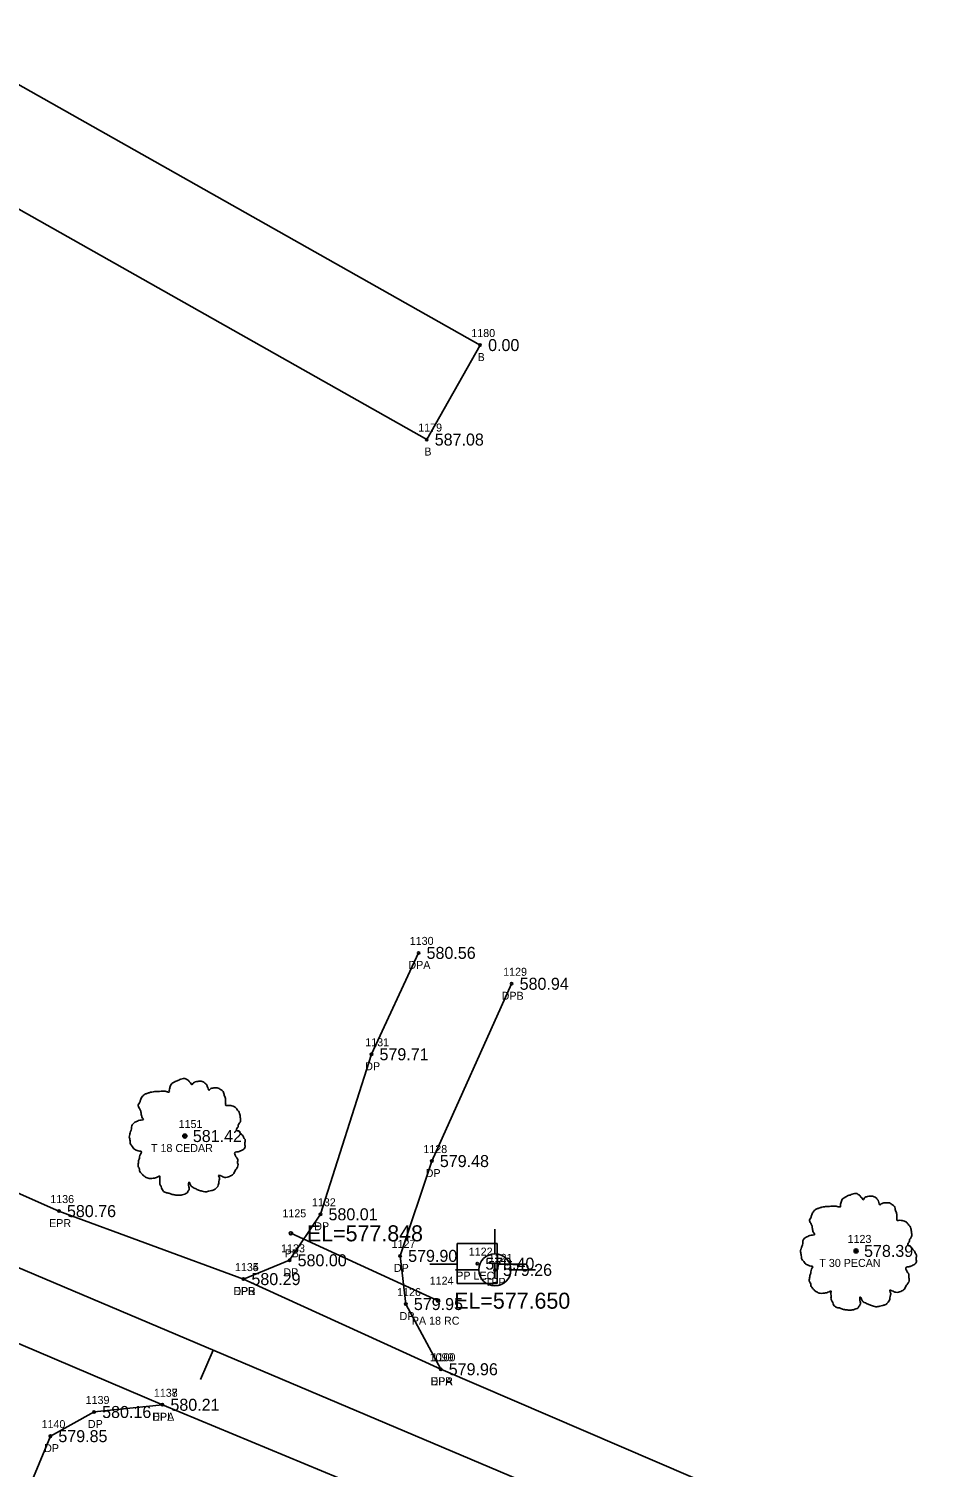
# Model space of a CAD drawing. Extents: x 1664393 to 1667175, y 987029 to 988607.
# Drawn here: x 1665100.7 to 1665215.9, y 987913.2 to 988093 of the extents above; entities that cross this region are included whole.
import ezdxf

# ---------------------------------------------------------------- set-up
doc = ezdxf.new("R2010")
doc.units = 0
for name, color, linetype in [('RD_EX_Bldg', 7, 'Continuous'), ('RD_EX_Bldg_txCode', 7, 'Continuous'), ('RD_EX_DR_Pipe', 7, 'Continuous'), ('RD_EX_DR_Pipe_txCode', 7, 'Continuous'), ('RD_EX_Driveway', 7, 'Continuous'), ('RD_EX_Driveway_txCode', 7, 'Continuous'), ('RD_EX_Road', 7, 'Continuous'), ('RD_EX_Road_txCode', 7, 'Continuous'), ('RD_EX_TX_Bldg_ELEV', 7, 'Continuous'), ('RD_EX_TX_Driveway_ELEV', 7, 'Continuous'), ('RD_EX_TX_Road_ELEV', 7, 'Continuous'), ('RD_EX_TX_UT_ELEV', 7, 'Continuous'), ('RD_EX_TX_VEG_ELEV', 7, 'Continuous'), ('RD_EX_UT', 7, 'Continuous'), ('RD_EX_UT_txCode', 7, 'Continuous'), ('RD_EX_VEG', 7, 'Continuous'), ('RD_EX_VEG_txCode', 7, 'Continuous'), ('RD_HC_Cl', 7, 'Continuous'), ('RD_HC_Data_Tic', 7, 'Continuous'), ('RD_HC_Survey_ELEV', 7, 'Continuous'), ('RD_SMD_Locator', 7, 'Continuous'), ('RD_TX_Pipe_ElevEX', 7, 'Continuous')]:
    doc.layers.add(name, color=color, linetype=linetype)

msp = doc.modelspace()

# ---------------------------------------------------------------- linework, layer by layer
at = {"layer": 'RD_EX_Bldg'}
msp.add_lwpolyline([(1665080.42, 988081.16), (1665150.45, 988041.63), (1665157.12, 988053.44), (1665087.09, 988092.97), (1665080.42, 988081.16)], dxfattribs=at)
at = {"layer": 'RD_EX_DR_Pipe'}
msp.add_line((1665151.88, 987934), (1665133.48, 987942.42), dxfattribs=at)
at = {"layer": 'RD_EX_Driveway'}
for points in [[(1665149.43, 987977.47), (1665143.55, 987964.8), (1665137.18, 987944.8), (1665133.32, 987939.05), (1665127.55, 987936.7)], [(1665152.2, 987925.43), (1665147.84, 987933.58), (1665147.13, 987939.6), (1665151.09, 987951.45), (1665161.06, 987973.61)], [(1665117.43, 987920.99), (1665108.9, 987920.09), (1665103.43, 987917.07), (1665098.7, 987905.61), (1665086.52, 987910.5), (1665090.17, 987920.87), (1665090.28, 987927.13), (1665086.22, 987934.27)]]:
    msp.add_lwpolyline(points, dxfattribs=at)
at = {"layer": 'RD_EX_Road'}
for points in [[(1665506.06, 987776.52), (1665471.95, 987789.57), (1665426.52, 987809.19), (1665380.33, 987828.78), (1665335.61, 987847.53), (1665288.25, 987866.82), (1665242.34, 987886.56), (1665197.07, 987906.16), (1665152.2, 987925.43), (1665127.55, 987936.7), (1665104.5, 987945.2), (1665059.19, 987965.3), (1665013.63, 987984.66), (1664966.38, 988005.06), (1664921.66, 988023.83), (1664875.55, 988043.8)], [(1665498.75, 987759.37), (1665465.87, 987774.2), (1665419.78, 987793.88), (1665373.62, 987813.14), (1665327.95, 987832.31), (1665281.42, 987852.3), (1665236.13, 987871.34), (1665189.6, 987890.71), (1665143.92, 987909.97), (1665117.43, 987920.99), (1665086.22, 987934.27), (1665051.62, 987948.55), (1665005.38, 987968.44), (1664960.17, 987987.67), (1664913.53, 988007.62), (1664868.21, 988026.81)]]:
    msp.add_lwpolyline(points, dxfattribs=at)
at = {"layer": 'RD_EX_UT'}
for p, q in [((1665158.97, 987942.92), (1665158.97, 987939.85)), ((1665159.26, 987941.14), (1665154.26, 987941.14)), ((1665154.26, 987941.14), (1665154.26, 987936.14)), ((1665159.26, 987936.14), (1665159.26, 987941.14)), ((1665150.82, 987938.58), (1665154.29, 987938.58)), ((1665154.04, 987937.86), (1665156.97, 987937.86)), ((1665159.18, 987938.58), (1665162.82, 987938.58)), ((1665160.97, 987937.86), (1665164.04, 987937.86)), ((1665154.26, 987936.14), (1665159.26, 987936.14))]:
    msp.add_line(p, q, dxfattribs=at)
msp.add_circle((1665158.97, 987937.85), 2, dxfattribs=at)
at = {"layer": 'RD_EX_VEG'}
for centre, radius in [((1665120.23, 987954.58), 0.25), ((1665120.22, 987954.56), 0.0001), ((1665204.09, 987940.22), 0.25), ((1665204.08, 987940.2), 0.0001)]:
    msp.add_circle(centre, radius, dxfattribs=at)
for points in [[(1665120.36, 987961.75), (1665120.06, 987961.78), (1665119.74, 987961.68), (1665119.49, 987961.58), (1665119.26, 987961.5), (1665119.04, 987961.4), (1665118.74, 987961.23), (1665118.51, 987961.03), (1665118.39, 987960.78), (1665118.34, 987960.55), (1665118.29, 987960.28), (1665118.29, 987960.1), (1665118.16, 987960.08), (1665118.01, 987960.1), (1665117.76, 987960.18), (1665117.51, 987960.18), (1665117.26, 987960.18), (1665116.91, 987960.15), (1665116.56, 987960.15), (1665116.29, 987960.1), (1665115.96, 987960.05), (1665115.59, 987959.93), (1665115.24, 987959.8), (1665114.94, 987959.55), (1665114.69, 987959.08), (1665114.56, 987958.73), (1665114.41, 987958.48), (1665114.56, 987958.03), (1665114.74, 987957.68), (1665114.76, 987957.48), (1665114.84, 987957.05), (1665114.94, 987956.83), (1665115.06, 987956.63), (1665114.99, 987956.6), (1665114.61, 987956.55), (1665114.31, 987956.45), (1665113.89, 987956.23), (1665113.66, 987956), (1665113.56, 987955.68), (1665113.54, 987955.33), (1665113.44, 987955.13), (1665113.36, 987954.85), (1665113.34, 987954.78), (1665113.29, 987954.45), (1665113.39, 987954), (1665113.41, 987953.65), (1665113.54, 987953.43), (1665113.69, 987953.25), (1665113.86, 987953), (1665114.26, 987952.78), (1665114.59, 987952.68), (1665114.79, 987952.65), (1665114.61, 987952.15), (1665114.56, 987951.8), (1665114.44, 987951.4), (1665114.44, 987951.33), (1665114.39, 987950.86), (1665114.54, 987950.53), (1665114.61, 987950.16), (1665114.79, 987949.93), (1665115.06, 987949.63), (1665115.39, 987949.41), (1665115.89, 987949.28), (1665116.29, 987949.31), (1665116.86, 987949.48), (1665117.11, 987949.56), (1665117.09, 987949.38), (1665117.11, 987949.01), (1665117.11, 987948.58), (1665117.26, 987948.26), (1665117.36, 987947.98), (1665117.51, 987947.73), (1665117.84, 987947.51), (1665118.24, 987947.43), (1665118.66, 987947.28), (1665119.11, 987947.21), (1665119.61, 987947.18), (1665120.21, 987947.33), (1665120.49, 987947.46), (1665120.59, 987947.63), (1665120.79, 987948.01), (1665120.74, 987948.23), (1665120.76, 987948.83), (1665120.86, 987948.66), (1665121.04, 987948.31), (1665121.54, 987948.01), (1665121.94, 987947.83), (1665122.41, 987947.68), (1665122.71, 987947.61), (1665123.19, 987947.68), (1665123.56, 987947.76), (1665123.93, 987947.88), (1665124.23, 987948.16), (1665124.41, 987948.43), (1665124.46, 987948.71), (1665124.53, 987949.08), (1665124.58, 987949.26)], [(1665124.58, 987949.26), (1665124.51, 987949.43), (1665124.46, 987949.68), (1665124.53, 987949.66), (1665124.71, 987949.61), (1665124.98, 987949.48), (1665125.21, 987949.41), (1665125.53, 987949.43), (1665125.81, 987949.53), (1665126.26, 987949.81), (1665126.53, 987950.28), (1665126.81, 987950.68), (1665126.88, 987951.01), (1665126.83, 987951.23), (1665126.81, 987951.73), (1665126.61, 987951.98), (1665126.56, 987952.1), (1665126.46, 987952.5), (1665126.53, 987952.55), (1665126.81, 987952.6), (1665127.18, 987952.73), (1665127.46, 987952.85), (1665127.68, 987953.03), (1665127.76, 987953.25), (1665127.73, 987953.65), (1665127.78, 987954.05), (1665127.71, 987954.2), (1665127.61, 987954.35), (1665127.53, 987954.55), (1665127.38, 987954.7), (1665127.28, 987954.85), (1665127.18, 987954.95), (1665127.06, 987955.1), (1665126.88, 987955.23), (1665126.73, 987955.28), (1665126.68, 987955.43), (1665126.83, 987955.63), (1665126.88, 987955.73), (1665126.91, 987955.95), (1665127.13, 987956.3), (1665127.18, 987956.7), (1665127.13, 987957.13), (1665127.08, 987957.4), (1665126.93, 987957.68), (1665126.73, 987957.93), (1665126.61, 987958.1), (1665126.43, 987958.23), (1665126.11, 987958.35), (1665125.86, 987958.4), (1665125.51, 987958.4), (1665125.31, 987958.45), (1665125.33, 987958.5), (1665125.33, 987958.65), (1665125.33, 987958.93), (1665125.26, 987959.38), (1665125.11, 987959.88), (1665125.11, 987959.9), (1665125.01, 987960.15), (1665124.78, 987960.35), (1665124.61, 987960.45), (1665124.41, 987960.58), (1665124.16, 987960.6), (1665123.86, 987960.6), (1665123.59, 987960.55), (1665123.39, 987960.45), (1665123.21, 987960.33), (1665123.14, 987960.48), (1665123.04, 987960.78), (1665122.99, 987960.93), (1665122.84, 987961.1), (1665122.61, 987961.3), (1665122.16, 987961.43), (1665121.54, 987961.35), (1665121.24, 987961.15), (1665121.09, 987960.98), (1665121.04, 987961.1), (1665120.84, 987961.3), (1665120.74, 987961.48), (1665120.56, 987961.6), (1665120.41, 987961.7), (1665120.31, 987961.75)], [(1665204.22, 987947.39), (1665203.92, 987947.41), (1665203.6, 987947.31), (1665203.35, 987947.21), (1665203.12, 987947.14), (1665202.9, 987947.04), (1665202.6, 987946.87), (1665202.37, 987946.67), (1665202.25, 987946.42), (1665202.2, 987946.19), (1665202.15, 987945.92), (1665202.15, 987945.74), (1665202.02, 987945.72), (1665201.87, 987945.74), (1665201.62, 987945.82), (1665201.37, 987945.82), (1665201.12, 987945.82), (1665200.77, 987945.79), (1665200.42, 987945.79), (1665200.15, 987945.74), (1665199.82, 987945.69), (1665199.45, 987945.57), (1665199.1, 987945.44), (1665198.8, 987945.19), (1665198.55, 987944.72), (1665198.42, 987944.37), (1665198.27, 987944.12), (1665198.42, 987943.67), (1665198.6, 987943.32), (1665198.62, 987943.12), (1665198.7, 987942.69), (1665198.8, 987942.47), (1665198.92, 987942.27), (1665198.85, 987942.24), (1665198.47, 987942.19), (1665198.17, 987942.09), (1665197.75, 987941.87), (1665197.52, 987941.64), (1665197.42, 987941.32), (1665197.4, 987940.97), (1665197.3, 987940.77), (1665197.22, 987940.49), (1665197.2, 987940.42), (1665197.15, 987940.09), (1665197.25, 987939.64), (1665197.27, 987939.29), (1665197.4, 987939.07), (1665197.55, 987938.89), (1665197.72, 987938.64), (1665198.12, 987938.42), (1665198.45, 987938.32), (1665198.65, 987938.29), (1665198.47, 987937.79), (1665198.42, 987937.44), (1665198.3, 987937.04), (1665198.3, 987936.97), (1665198.25, 987936.49), (1665198.4, 987936.17), (1665198.47, 987935.79), (1665198.65, 987935.57), (1665198.92, 987935.27), (1665199.25, 987935.05), (1665199.75, 987934.92), (1665200.15, 987934.95), (1665200.72, 987935.12), (1665200.97, 987935.2), (1665200.95, 987935.02), (1665200.97, 987934.65), (1665200.97, 987934.22), (1665201.12, 987933.9), (1665201.22, 987933.62), (1665201.37, 987933.37), (1665201.7, 987933.15), (1665202.1, 987933.07), (1665202.52, 987932.92), (1665202.97, 987932.85), (1665203.47, 987932.82), (1665204.07, 987932.97), (1665204.35, 987933.1), (1665204.45, 987933.27), (1665204.65, 987933.65), (1665204.6, 987933.87), (1665204.62, 987934.47), (1665204.72, 987934.3), (1665204.89, 987933.95), (1665205.39, 987933.65), (1665205.79, 987933.47), (1665206.27, 987933.32), (1665206.57, 987933.25), (1665207.04, 987933.32), (1665207.42, 987933.4), (1665207.79, 987933.52), (1665208.09, 987933.8), (1665208.27, 987934.07), (1665208.32, 987934.35), (1665208.39, 987934.72), (1665208.44, 987934.9)], [(1665208.44, 987934.9), (1665208.37, 987935.07), (1665208.32, 987935.32), (1665208.39, 987935.3), (1665208.57, 987935.25), (1665208.84, 987935.12), (1665209.07, 987935.05), (1665209.39, 987935.07), (1665209.67, 987935.17), (1665210.12, 987935.45), (1665210.39, 987935.92), (1665210.67, 987936.32), (1665210.74, 987936.64), (1665210.69, 987936.87), (1665210.67, 987937.37), (1665210.47, 987937.62), (1665210.42, 987937.74), (1665210.32, 987938.14), (1665210.39, 987938.19), (1665210.67, 987938.24), (1665211.04, 987938.37), (1665211.32, 987938.49), (1665211.54, 987938.67), (1665211.62, 987938.89), (1665211.59, 987939.29), (1665211.64, 987939.69), (1665211.57, 987939.84), (1665211.47, 987939.99), (1665211.39, 987940.19), (1665211.24, 987940.34), (1665211.14, 987940.49), (1665211.04, 987940.59), (1665210.92, 987940.74), (1665210.74, 987940.87), (1665210.59, 987940.92), (1665210.54, 987941.07), (1665210.69, 987941.27), (1665210.74, 987941.37), (1665210.77, 987941.59), (1665210.99, 987941.94), (1665211.04, 987942.34), (1665210.99, 987942.77), (1665210.94, 987943.04), (1665210.79, 987943.32), (1665210.59, 987943.57), (1665210.47, 987943.74), (1665210.29, 987943.87), (1665209.97, 987943.99), (1665209.72, 987944.04), (1665209.37, 987944.04), (1665209.17, 987944.09), (1665209.19, 987944.14), (1665209.19, 987944.29), (1665209.19, 987944.57), (1665209.12, 987945.02), (1665208.97, 987945.52), (1665208.97, 987945.54), (1665208.87, 987945.79), (1665208.64, 987945.99), (1665208.47, 987946.09), (1665208.27, 987946.22), (1665208.02, 987946.24), (1665207.72, 987946.24), (1665207.44, 987946.19), (1665207.24, 987946.09), (1665207.07, 987945.97), (1665206.99, 987946.12), (1665206.89, 987946.42), (1665206.84, 987946.57), (1665206.69, 987946.74), (1665206.47, 987946.94), (1665206.02, 987947.06), (1665205.39, 987946.99), (1665205.09, 987946.79), (1665204.94, 987946.62), (1665204.89, 987946.74), (1665204.69, 987946.94), (1665204.6, 987947.11), (1665204.42, 987947.24), (1665204.27, 987947.34), (1665204.17, 987947.39)]]:
    msp.add_spline(points, degree=3, dxfattribs=at)
at = {"layer": 'RD_HC_Cl'}
msp.add_line((1666160.05, 987489.41), (1664963.07, 987995.8), dxfattribs=at)
at = {"layer": 'RD_HC_Data_Tic'}
msp.add_line((1665123.76, 987927.82), (1665122.2, 987924.13), dxfattribs=at)
at = {"layer": 'RD_SMD_Locator'}
for centre, radius in [((1665157.12, 988053.44), 0.15), ((1665150.45, 988041.63), 0.15), ((1665149.43, 987977.47), 0.15), ((1665161.06, 987973.61), 0.15), ((1665143.55, 987964.8), 0.15), ((1665120.23, 987954.58), 0.15), ((1665151.09, 987951.45), 0.15), ((1665104.5, 987945.2), 0.15), ((1665137.18, 987944.8), 0.15), ((1665133.48, 987942.42), 0.2), ((1665147.13, 987939.6), 0.15), ((1665204.09, 987940.22), 0.15), ((1665133.32, 987939.05), 0.15), ((1665156.76, 987938.63), 0.15), ((1665158.97, 987937.85), 0.15), ((1665127.55, 987936.7), 0.15), ((1665127.55, 987936.7), 0.15), ((1665151.88, 987934), 0.2), ((1665147.84, 987933.58), 0.15), ((1665152.2, 987925.43), 0.15), ((1665152.2, 987925.43), 0.15), ((1665108.9, 987920.09), 0.15), ((1665117.43, 987920.99), 0.15), ((1665117.43, 987920.99), 0.15), ((1665103.43, 987917.07), 0.15)]:
    msp.add_circle(centre, radius, dxfattribs=at)

# ---------------------------------------------------------------- texts
at = {"layer": 'RD_EX_Bldg_txCode'}
for s, p in [('1180', (1665156.02, 988054.44)), ('B', (1665156.81, 988051.44)), ('1179', (1665149.39, 988042.63)), ('B', (1665150.15, 988039.63))]:
    msp.add_text(s, height=1, dxfattribs=at).set_placement(p)
at = {"layer": 'RD_EX_DR_Pipe_txCode'}
for s, p in [('1125', (1665132.42, 987944.42)), ('PB', (1665132.7, 987939.42)), ('1124', (1665150.82, 987936)), ('PA 18 RC', (1665148.59, 987931))]:
    msp.add_text(s, height=1, dxfattribs=at).set_placement(p)
at = {"layer": 'RD_EX_Driveway_txCode'}
for s, p in [('1130', (1665148.33, 987978.47)), ('DPA', (1665148.16, 987975.47)), ('1129', (1665160, 987974.61)), ('DPB', (1665159.81, 987971.61)), ('1131', (1665142.77, 987965.8)), ('DP', (1665142.77, 987962.8)), ('1128', (1665150.03, 987952.45)), ('DP', (1665150.32, 987949.45)), ('1132', (1665136.11, 987945.8)), ('DP', (1665136.4, 987942.8)), ('1127', (1665146.07, 987940.6)), ('1133', (1665132.26, 987940.05)), ('1134', (1665126.49, 987937.7)), ('DP', (1665132.54, 987937.05)), ('DP', (1665146.35, 987937.6)), ('DPB', (1665126.3, 987934.7)), ('1126', (1665146.75, 987934.58)), ('DP', (1665147.06, 987931.58)), ('1100', (1665151.06, 987926.43)), ('DPA', (1665150.93, 987923.43)), ('1139', (1665107.84, 987921.09)), ('1138', (1665116.36, 987921.99)), ('DPA', (1665116.16, 987918.99)), ('1140', (1665102.33, 987918.07)), ('DP', (1665108.12, 987918.09)), ('DP', (1665102.65, 987915.07))]:
    msp.add_text(s, height=1, dxfattribs=at).set_placement(p)
at = {"layer": 'RD_EX_Road_txCode'}
for s, p in [('1136', (1665103.42, 987946.2)), ('EPR', (1665103.27, 987943.2)), ('1135', (1665126.49, 987937.7)), ('EPR', (1665126.32, 987934.7)), ('1099', (1665150.82, 987926.43)), ('EPR', (1665150.97, 987923.43)), ('1137', (1665116.36, 987921.99)), ('EPL', (1665116.22, 987918.99))]:
    msp.add_text(s, height=1, dxfattribs=at).set_placement(p)
at = {"layer": 'RD_EX_TX_Bldg_ELEV'}
for s, p in [('0.00', (1665158.12, 988052.69)), ('587.08', (1665151.45, 988040.88))]:
    msp.add_text(s, height=1.5, dxfattribs=at).set_placement(p)
at = {"layer": 'RD_EX_TX_Driveway_ELEV'}
for s, p in [('580.56', (1665150.43, 987976.72)), ('580.94', (1665162.06, 987972.86)), ('579.71', (1665144.55, 987964.05)), ('579.48', (1665152.09, 987950.7)), ('580.01', (1665138.18, 987944.05)), ('580.00', (1665134.32, 987938.3)), ('579.90', (1665148.13, 987938.85)), ('580.29', (1665128.55, 987935.95)), ('579.95', (1665148.84, 987932.83)), ('579.96', (1665153.2, 987924.68)), ('580.21', (1665118.43, 987920.24)), ('580.16', (1665109.9, 987919.34)), ('579.85', (1665104.43, 987916.32))]:
    msp.add_text(s, height=1.5, dxfattribs=at).set_placement(p)
at = {"layer": 'RD_EX_TX_Road_ELEV'}
for s, p in [('580.76', (1665105.5, 987944.45)), ('580.29', (1665128.55, 987935.95)), ('579.96', (1665153.2, 987924.68)), ('580.21', (1665118.43, 987920.24))]:
    msp.add_text(s, height=1.5, dxfattribs=at).set_placement(p)
at = {"layer": 'RD_EX_TX_UT_ELEV'}
msp.add_text('579.26', height=1.5, dxfattribs=at).set_placement((1665159.97, 987937.1))
at = {"layer": 'RD_EX_TX_VEG_ELEV'}
for s, p in [('581.42', (1665121.23, 987953.83)), ('578.39', (1665205.09, 987939.47))]:
    msp.add_text(s, height=1.5, dxfattribs=at).set_placement(p)
at = {"layer": 'RD_EX_UT'}
msp.add_text('T', height=2, dxfattribs=at).set_placement((1665158.12, 987936.8))
at = {"layer": 'RD_EX_UT_txCode'}
for s, p in [('1122', (1665155.7, 987939.63)), ('1121', (1665158.19, 987938.85)), ('PP LEC', (1665154.14, 987936.63)), ('TPP', (1665157.7, 987935.85))]:
    msp.add_text(s, height=1, dxfattribs=at).set_placement(p)
at = {"layer": 'RD_EX_VEG_txCode'}
for s, p in [('1151', (1665119.45, 987955.58)), ('T 18 CEDAR', (1665116, 987952.58)), ('1123', (1665203.03, 987941.22)), ('T 30 PECAN', (1665199.5, 987938.22))]:
    msp.add_text(s, height=1, dxfattribs=at).set_placement(p)
at = {"layer": 'RD_HC_Survey_ELEV'}
msp.add_text('579.40', height=1.5, dxfattribs=at).set_placement((1665157.76, 987937.88))
at = {"layer": 'RD_TX_Pipe_ElevEX'}
for s, p in [('EL=577.848', (1665135.48, 987941.42)), ('EL=577.650', (1665153.88, 987933))]:
    msp.add_text(s, height=2, dxfattribs=at).set_placement(p)

doc.saveas('drawing.dxf')
